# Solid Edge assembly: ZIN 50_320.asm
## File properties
Title: Zylinder
Author: bmolnar
Template: iso metric assembly.asm
Last saved by: bmolnar
Revision: 31
Application: Solid Edge
Username: bmolnar
Dokumentum tartalom típus: 1
Document Number: ZIN 50/320
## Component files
Profilrohr.par
Kolbenstange.par
Kit_2.par
Kit_1.par
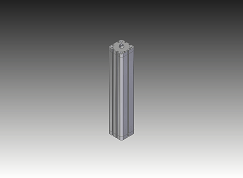
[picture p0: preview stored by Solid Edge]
